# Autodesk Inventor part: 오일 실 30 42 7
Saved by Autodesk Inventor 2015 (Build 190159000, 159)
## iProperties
Created: 2025-06
Part Number: 오일 실 30 42 7
Material: 일반
Document SubType Name: Modeling
Designer: User
Density: 1 g/cm^3
Appearance: 기본값
Author: User
Author: jhkim
Description: 오일 실 - 스프링 장착, 금속 케이스 SM
Creation Date: 2025-05-23
Sending System: Autodesk Inventor 2026
Preprocessor: ST-DEVELOPER v20.1
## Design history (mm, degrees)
node "오일 실 30 42 71"
body "Solid1"
node "기준1"
